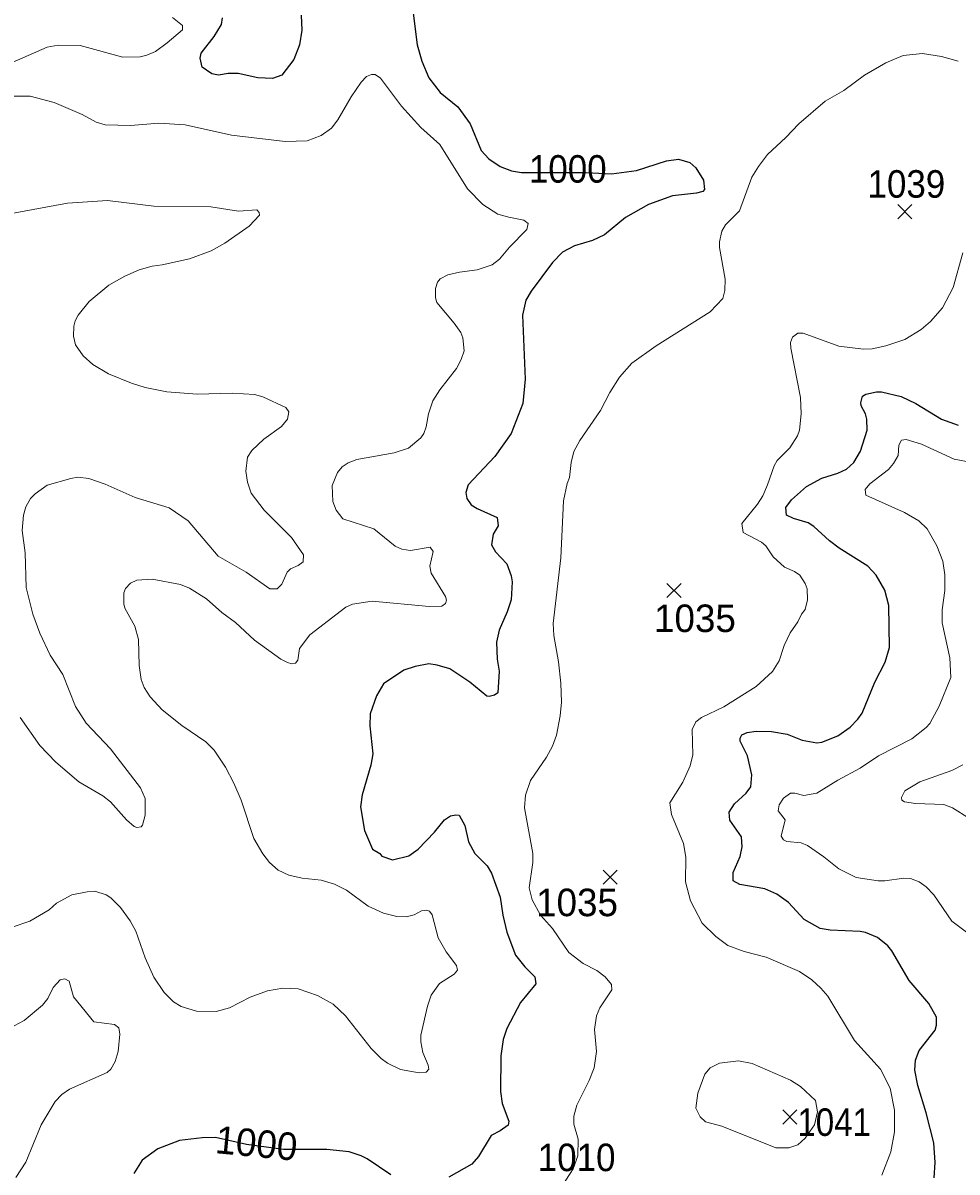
# Model space of a CAD drawing. Extents: x 265 to 291.4, y 7731.5 to 7759.6.
# Drawn here: x 269.927 to 272.644, y 7742.944 to 7746.284 of the extents above; entities that cross this region are included whole.
import ezdxf
from ezdxf.enums import TextEntityAlignment as Align

# ---------------------------------------------------------------- set-up
doc = ezdxf.new("R2010")
doc.units = 0
doc.header["$LTSCALE"] = 0.032
for name, color, linetype, lineweight in [('1', 7, 'Continuous', 25), ('2', 7, 'Continuous', 13), ('21', 7, 'Continuous', 25), ('61', 7, 'Continuous', 13)]:
    doc.layers.add(name, color=color, linetype=linetype, lineweight=lineweight)

msp = doc.modelspace()

# ---------------------------------------------------------------- linework, layer by layer
at = {"layer": '1'}
for points in [[(271.0575, 7746.352), (271.0742, 7746.22), (271.0877, 7746.1722), (271.1076, 7746.1245), (271.141, 7746.0815), (271.1919, 7746.0402), (271.2285, 7745.9909), (271.2603, 7745.9129), (271.2826, 7745.889), (271.3152, 7745.866), (271.3487, 7745.854), (271.3773, 7745.8492), (271.565, 7745.8489), (271.6394, 7745.8456), (271.7114, 7745.8548), (271.7989, 7745.8827), (271.8339, 7745.8874), (271.8673, 7745.8779), (271.884, 7745.8628), (271.9071, 7745.827), (271.9095, 7745.7992), (271.9047, 7745.7936), (271.8864, 7745.7888), (271.8164, 7745.7808), (271.7464, 7745.7562), (271.6796, 7745.718), (271.6191, 7745.6679), (271.5841, 7745.6512), (271.5316, 7745.6361), (271.4966, 7745.617), (271.468, 7745.5875), (271.4051, 7745.504), (271.39, 7745.4778), (271.3805, 7745.434), (271.3884, 7745.2479), (271.3813, 7745.1779), (271.3478, 7745.0904), (271.3001, 7745.0236), (271.2222, 7744.9408), (271.2158, 7744.9186), (271.2182, 7744.9011), (271.2309, 7744.8836), (271.2484, 7744.8724), (271.3065, 7744.8461), (271.3097, 7744.8223), (271.2953, 7744.7976), (271.2898, 7744.7666), (271.3017, 7744.7467), (271.3343, 7744.7117), (271.3478, 7744.6767)], [(270.4426, 7746.1818), (270.4458, 7746.1961), (270.4839, 7746.2446), (270.5046, 7746.2788), (270.5078, 7746.2987)], [(270.7361, 7746.3059), (270.7385, 7746.2629), (270.7313, 7746.22), (270.7154, 7746.177), (270.6805, 7746.1317), (270.6534, 7746.1221), (270.6105, 7746.1237)], [(270.6105, 7746.1237), (270.5532, 7746.1364), (270.5245, 7746.1372), (270.4959, 7746.1324), (270.4768, 7746.1356), (270.4482, 7746.1555), (270.4426, 7746.1818)], [(272.382, 7745.1317), (272.378, 7745.1477), (272.3653, 7745.1707), (272.3645, 7745.1795), (272.3692, 7745.1986), (272.3788, 7745.2049), (272.4098, 7745.2113), (272.4242, 7745.2113), (272.4814, 7745.1978), (272.5244, 7745.1779), (272.5992, 7745.1317), (272.6469, 7745.115)], [(272.2507, 7744.9607), (272.2969, 7744.975), (272.3223, 7744.9869), (272.3438, 7745.006), (272.3629, 7745.0395), (272.3828, 7745.0999), (272.382, 7745.1317)], [(272.5777, 7742.9267), (272.5808, 7742.9712), (272.5761, 7743.0285), (272.5546, 7743.116), (272.5299, 7743.1955), (272.5212, 7743.2401), (272.5236, 7743.2687), (272.5339, 7743.2974), (272.58, 7743.3562), (272.5848, 7743.3705), (272.5848, 7743.3936), (272.5617, 7743.4342), (272.5045, 7743.501), (272.4544, 7743.5869), (272.4432, 7743.6012), (272.413, 7743.6259), (272.378, 7743.6402), (272.3621, 7743.6434), (272.2746, 7743.6466), (272.246, 7743.6521), (272.199, 7743.6784), (272.1537, 7743.7269), (272.1203, 7743.7516), (272.0853, 7743.7675), (272.0121, 7743.7794), (271.993, 7743.7906), (271.993, 7743.8144), (272.0129, 7743.8606), (272.0192, 7743.8892), (272.0168, 7743.9178), (271.9834, 7743.9664), (271.981, 7743.9902), (271.9969, 7744.0141), (272.0312, 7744.0451), (272.0439, 7744.0634), (272.0471, 7744.0984), (272.0351, 7744.1533), (272.0129, 7744.1963), (272.0129, 7744.205), (272.0184, 7744.2146), (272.0336, 7744.2217), (272.0598, 7744.2257), (272.1044, 7744.2241), (272.1505, 7744.2161), (272.1935, 7744.1994), (272.2364, 7744.1915), (272.2507, 7744.193), (272.2969, 7744.2121), (272.3335, 7744.2368), (272.3557, 7744.2599), (272.3677, 7744.2774), (272.405, 7744.3681), (272.4353, 7744.4254), (272.4472, 7744.4683), (272.4456, 7744.5908), (272.4337, 7744.6354), (272.409, 7744.6783), (272.3844, 7744.7053), (272.3017, 7744.757), (272.273, 7744.7785), (272.2276, 7744.8199), (272.211, 7744.831), (272.168, 7744.843), (272.1481, 7744.8533), (272.1457, 7744.8756), (272.1624, 7744.8979), (272.2062, 7744.9368), (272.2507, 7744.9607)], [(271.3478, 7744.6767), (271.3502, 7744.6592), (271.3478, 7744.6067), (271.3359, 7744.5717), (271.3121, 7744.5192), (271.3049, 7744.4842), (271.3065, 7744.4349)], [(271.3065, 7744.4349), (271.3121, 7744.3999), (271.3089, 7744.3371), (271.2985, 7744.3299), (271.2834, 7744.3259), (271.277, 7744.3275), (271.2269, 7744.3681), (271.1689, 7744.4062), (271.1323, 7744.4174), (271.1076, 7744.4206), (271.0686, 7744.4134), (271.0352, 7744.4023), (270.9763, 7744.3625), (270.9557, 7744.3283), (270.9374, 7744.2758), (270.9358, 7744.2408), (270.9453, 7744.1597), (270.939, 7744.1263), (270.9143, 7744.0403), (270.9095, 7744.0053), (270.9207, 7743.9369), (270.9437, 7743.882), (270.9652, 7743.8693), (270.9716, 7743.8621), (271.0018, 7743.851), (271.0496, 7743.8629), (271.0766, 7743.8828), (271.1243, 7743.9313), (271.1537, 7743.9672), (271.1713, 7743.9791), (271.1864, 7743.9822), (271.1959, 7743.9807), (271.2126, 7743.9512), (271.2237, 7743.9035), (271.242, 7743.8701), (271.2771, 7743.8343), (271.2906, 7743.8128), (271.3152, 7743.7428), (271.3232, 7743.6903), (271.3351, 7743.641), (271.3598, 7743.5742), (271.3868, 7743.54), (271.4163, 7743.5113), (271.4186, 7743.4907), (271.3749, 7743.4366), (271.3351, 7743.361), (271.324, 7743.3292), (271.3168, 7743.2815), (271.316, 7743.178), (271.3216, 7743.143), (271.3407, 7743.0921), (271.3383, 7743.0802), (271.3153, 7743.0635), (271.289, 7743.05), (271.2524, 7742.9887), (271.2333, 7742.9672), (271.1657, 7742.929)], [(270.9971, 7742.9354), (270.9286, 7742.9823), (270.9111, 7742.9911), (270.8761, 7743.0022), (270.8109, 7743.0094), (270.6849, 7743.0099), (270.578, 7743.0239), (270.4877, 7743.0445), (270.4489, 7743.0438), (270.3829, 7743.0356), (270.3193, 7743.0118), (270.2739, 7742.9783), (270.2501, 7742.9394)]]:
    msp.add_lwpolyline(points, dxfattribs=at)
at = {"layer": '2'}
for points in [[(270.3623, 7746.2995), (270.3917, 7746.2764), (270.3917, 7746.2637), (270.3471, 7746.2255), (270.3129, 7746.2009), (270.2875, 7746.1897), (270.2684, 7746.185), (270.2175, 7746.1842), (270.0934, 7746.2184), (270.0297, 7746.2192), (269.9979, 7746.2136), (269.8722, 7746.1579)], [(272.6469, 7746.1722), (272.5992, 7746.1866), (272.5435, 7746.1945), (272.4878, 7746.1889), (272.4369, 7746.1675), (272.3748, 7746.1317), (272.3144, 7746.0871), (272.2603, 7746.0561), (272.1839, 7745.9909), (272.1457, 7745.9503), (272.0932, 7745.9018), (272.0662, 7745.8668), (272.0471, 7745.835), (272.0113, 7745.7379)], [(269.8929, 7746.0712), (269.9486, 7746.0712), (270.0186, 7746.0521), (270.0997, 7746.0179), (270.1403, 7745.9956), (270.1666, 7745.9877), (270.2398, 7745.9853), (270.3225, 7745.9924), (270.3989, 7745.9877), (270.5341, 7745.9575), (270.69, 7745.9392), (270.7536, 7745.9407), (270.795, 7745.9567), (270.8252, 7745.9781), (270.8435, 7746.002), (270.8817, 7746.0688), (270.9111, 7746.1118), (270.9263, 7746.1285), (270.9414, 7746.1341), (270.9517, 7746.1341), (270.9676, 7746.1229), (271.0281, 7746.0418), (271.0845, 7745.9797), (271.1394, 7745.9304), (271.2206, 7745.8015), (271.2651, 7745.7562), (271.3089, 7745.7284), (271.3407, 7745.7188), (271.3837, 7745.7109), (271.3972, 7745.7005), (271.3932, 7745.683), (271.3423, 7745.6321), (271.3137, 7745.5971), (271.2922, 7745.5804)], [(270.3082, 7745.7514), (270.1729, 7745.7681), (270.0568, 7745.7602), (269.8945, 7745.7299), (269.7943, 7745.7411), (269.7466, 7745.7506), (269.6479, 7745.7904)], [(269.9192, 7744.2655), (269.9764, 7744.1835), (270.0226, 7744.135), (270.0902, 7744.0785), (270.1602, 7744.0372), (270.1825, 7744.0197), (270.2286, 7743.9672), (270.2509, 7743.9481), (270.2588, 7743.9457), (270.2708, 7743.9473), (270.2755, 7743.952), (270.2827, 7743.9815), (270.2827, 7744.0292), (270.2692, 7744.061), (270.1817, 7744.174), (270.1109, 7744.2488), (270.0806, 7744.2973), (270.0433, 7744.3904), (270.0067, 7744.446), (269.9764, 7744.5097), (269.9566, 7744.5654), (269.9367, 7744.6433), (269.9343, 7744.7436), (269.9247, 7744.8088), (269.9287, 7744.8533), (269.9359, 7744.8772), (269.9494, 7744.9011), (269.9629, 7744.9154), (269.9979, 7744.94), (270.0663, 7744.9599), (270.087, 7744.9631), (270.1188, 7744.9599), (270.1666, 7744.9432), (270.2541, 7744.9042), (270.3527, 7744.8748), (270.4084, 7744.8366), (270.4951, 7744.734), (270.577, 7744.6871), (270.6455, 7744.6385), (270.6669, 7744.6385), (270.6804, 7744.6521), (270.6956, 7744.6879), (270.7051, 7744.6974), (270.7282, 7744.707), (270.7425, 7744.7173), (270.7433, 7744.738), (270.7083, 7744.7881), (270.6287, 7744.8676), (270.5914, 7744.917), (270.5802, 7744.9488), (270.5754, 7744.9806), (270.5802, 7745.022), (270.5929, 7745.0411), (270.628, 7745.0737), (270.6789, 7745.1111), (270.6964, 7745.1317), (270.7003, 7745.1532), (270.6924, 7745.1659), (270.6248, 7745.197), (270.6009, 7745.2041), (270.5373, 7745.2073), (270.4339, 7745.2049), (270.3463, 7745.2113), (270.2827, 7745.224), (270.2429, 7745.2367), (270.1761, 7745.2638), (270.1308, 7745.2908), (270.1021, 7745.3163), (270.0806, 7745.3481), (270.0743, 7745.3736), (270.0751, 7745.4022), (270.0791, 7745.4181), (270.0878, 7745.434), (270.1196, 7745.4738), (270.1769, 7745.5215), (270.2238, 7745.5478), (270.2652, 7745.5661), (270.3034, 7745.5772), (270.332, 7745.5804), (270.4116, 7745.5979), (270.4752, 7745.6218), (270.515, 7745.644), (270.585, 7745.6926), (270.6152, 7745.7252), (270.6144, 7745.7331), (270.6073, 7745.7403), (270.5548, 7745.7371), (270.4736, 7745.749), (270.3082, 7745.7514)], [(272.0113, 7745.7379), (271.9707, 7745.6965), (271.9596, 7745.679), (271.9532, 7745.6472), (271.9532, 7745.6313), (271.9699, 7745.539), (271.9691, 7745.5056)], [(272.4218, 7743.2425), (272.3462, 7743.326), (272.2682, 7743.4549), (272.2483, 7743.4787), (272.2221, 7743.5026), (272.1855, 7743.5265), (272.0885, 7743.5686), (272.0248, 7743.5853), (271.9771, 7743.6028), (271.9429, 7743.6283), (271.9031, 7743.6673), (271.8689, 7743.7317), (271.8546, 7743.7874), (271.8554, 7743.859), (271.8482, 7743.8987), (271.8132, 7743.9831), (271.8092, 7744.0173), (271.8466, 7744.0769), (271.8681, 7744.1247), (271.8753, 7744.1565), (271.8737, 7744.2297), (271.884, 7744.2527), (271.9007, 7744.2655), (271.9659, 7744.2957), (272.0598, 7744.3553), (272.1076, 7744.3991), (272.1266, 7744.4301), (272.141, 7744.4747), (272.1585, 7744.5113), (272.1815, 7744.5431), (272.1919, 7744.5654), (272.2022, 7744.5789), (272.2094, 7744.6067), (272.2078, 7744.6385), (272.2022, 7744.6545), (272.1871, 7744.6783), (272.1712, 7744.6895), (272.1426, 7744.7022), (272.1091, 7744.7324), (272.0877, 7744.7642), (272.0757, 7744.7746), (272.0216, 7744.8024), (272.0184, 7744.8287), (272.0638, 7744.8851), (272.0789, 7744.909), (272.0932, 7744.9408), (272.1123, 7744.9965), (272.1211, 7745.0124), (272.1577, 7745.049), (272.1799, 7745.084), (272.1855, 7745.0999), (272.1911, 7745.1477), (272.1887, 7745.1954), (272.1608, 7745.3386), (272.16, 7745.3545), (272.1656, 7745.3704), (272.1807, 7745.3823), (272.1966, 7745.3823), (272.3001, 7745.3441), (272.3717, 7745.3354), (272.3971, 7745.337), (272.4369, 7745.3449), (272.4926, 7745.364), (272.5395, 7745.3927), (272.5665, 7745.4157), (272.6015, 7745.4555), (272.6326, 7745.5152), (272.6612, 7745.6154)], [(271.2922, 7745.5804), (271.2484, 7745.5661), (271.1975, 7745.5597), (271.1633, 7745.5518), (271.141, 7745.5398), (271.1331, 7745.5303), (271.1275, 7745.512)], [(271.1275, 7745.512), (271.1275, 7745.4849), (271.1307, 7745.4714), (271.1816, 7745.411), (271.2007, 7745.3839), (271.2071, 7745.3688), (271.2102, 7745.3306), (271.2023, 7745.3052), (271.1888, 7745.2797), (271.1394, 7745.2177), (271.1196, 7745.1858), (271.1068, 7745.1477), (271.1005, 7745.1095), (271.0933, 7745.0904), (271.0846, 7745.0777), (271.0488, 7745.0474), (271.0066, 7745.0339), (270.8984, 7745.0148), (270.873, 7745.0053), (270.8563, 7744.9933), (270.8419, 7744.9774), (270.8268, 7744.9392), (270.8284, 7744.8931), (270.838, 7744.8676), (270.8578, 7744.8422), (270.9477, 7744.8135), (271.0098, 7744.7626), (271.0289, 7744.7539), (271.0543, 7744.7507), (271.1116, 7744.7602), (271.1204, 7744.7475), (271.1108, 7744.7052), (271.1148, 7744.6847), (271.1561, 7744.6163), (271.1596, 7744.6058), (271.1566, 7744.5959), (271.146, 7744.5886), (271.1084, 7744.5876), (270.943, 7744.6035), (270.8857, 7744.594), (270.8666, 7744.586), (270.7616, 7744.5057), (270.7314, 7744.4651), (270.7266, 7744.4317), (270.7202, 7744.423), (270.7091, 7744.4214), (270.6964, 7744.4245), (270.6773, 7744.4349), (270.6009, 7744.4898), (270.546, 7744.5415), (270.5054, 7744.5701), (270.4617, 7744.6099), (270.4116, 7744.6409), (270.3861, 7744.6513), (270.3034, 7744.6672), (270.2588, 7744.664), (270.2398, 7744.6552), (270.2254, 7744.6401), (270.2207, 7744.6274), (270.2207, 7744.5956), (270.2238, 7744.5829), (270.2525, 7744.5304), (270.2636, 7744.4922), (270.2652, 7744.4158), (270.2716, 7744.3752), (270.2795, 7744.3522), (270.2978, 7744.3251), (270.3328, 7744.2869), (270.3893, 7744.2416), (270.4593, 7744.1939), (270.4832, 7744.17), (270.5166, 7744.1207), (270.5412, 7744.0745), (270.5619, 7744.0252), (270.5993, 7743.9131), (270.6248, 7743.8685), (270.6446, 7743.8431), (270.6701, 7743.8216), (270.7011, 7743.8065), (270.7393, 7743.7977), (270.795, 7743.7921), (270.8332, 7743.781), (270.8682, 7743.7627), (270.9318, 7743.7166), (270.9764, 7743.6967), (271.0146, 7743.6871), (271.0416, 7743.6855), (271.0655, 7743.6919), (271.0862, 7743.703), (271.1021, 7743.7046), (271.11, 7743.7022), (271.118, 7743.6919), (271.1355, 7743.6243), (271.1585, 7743.5837), (271.188, 7743.544)], [(271.9691, 7745.5056), (271.9628, 7745.4826), (271.9262, 7745.4436), (271.7687, 7745.3449), (271.6979, 7745.2948), (271.6621, 7745.2543), (271.6342, 7745.2097), (271.6072, 7745.1572), (271.5467, 7745.0697), (271.53, 7745.0379), (271.5221, 7745.0061), (271.5173, 7744.9623), (271.5101, 7744.9456), (271.4998, 7744.8947), (271.4918, 7744.7292), (271.4696, 7744.5383), (271.4712, 7744.5033), (271.4847, 7744.4269), (271.4918, 7744.3649), (271.4934, 7744.3092), (271.4902, 7744.2694), (271.4791, 7744.2138), (271.468, 7744.1819), (271.4505, 7744.1501), (271.4035, 7744.0817), (271.3892, 7744.0388), (271.386, 7744.0022), (271.4107, 7743.8701), (271.4107, 7743.8439), (271.3996, 7743.7699), (271.4083, 7743.7349), (271.4322, 7743.6903), (271.468, 7743.6513), (271.5149, 7743.5821), (271.5571, 7743.5503), (271.5969, 7743.5296), (271.6207, 7743.5113), (271.639, 7743.4891), (271.6398, 7743.4732), (271.6048, 7743.4215), (271.5953, 7743.3976), (271.5897, 7743.3578), (271.5953, 7743.2942), (271.5889, 7743.2472), (271.5746, 7743.2099), (271.538, 7743.1383), (271.5292, 7743.1064), (271.53, 7743.0834), (271.542, 7743.0396), (271.5412, 7742.9909), (271.5272, 7742.953), (271.4871, 7742.8901)], [(272.7065, 7743.6147), (272.6294, 7743.6728), (272.5761, 7743.7492), (272.5546, 7743.7731), (272.5339, 7743.7874), (272.5085, 7743.7969), (272.4894, 7743.7985), (272.4337, 7743.7906), (272.4146, 7743.7906), (272.351, 7743.8001), (272.3001, 7743.8248), (272.2571, 7743.8598), (272.2094, 7743.8932), (272.1903, 7743.9003), (272.1489, 7743.9051), (272.1394, 7743.9099), (272.133, 7743.9202), (272.1441, 7743.968), (272.1242, 7743.9934), (272.1266, 7744.0109), (272.1394, 7744.0308), (272.1601, 7744.0451), (272.1728, 7744.0451), (272.1982, 7744.0387), (272.2364, 7744.0451), (272.2977, 7744.0833), (272.3621, 7744.1175), (272.4154, 7744.1533), (272.5124, 7744.2034), (272.5546, 7744.236), (272.5649, 7744.2472), (272.592, 7744.2981), (272.6262, 7744.3808), (272.623, 7744.4381), (272.6007, 7744.5399), (272.6007, 7744.5781), (272.6087, 7744.6338), (272.6087, 7744.6799), (272.6023, 7744.7197), (272.5856, 7744.7642), (272.557, 7744.8136), (272.5331, 7744.8366), (272.491, 7744.8613), (272.3788, 7744.9114), (272.3772, 7744.9273), (272.3907, 7744.944), (272.4448, 7744.9854), (272.4591, 7745.0029), (272.4727, 7745.0267), (272.4743, 7745.057), (272.4822, 7745.0713), (272.4957, 7745.0729), (272.5403, 7745.0593), (272.6358, 7745.0156), (272.6867, 7745.006)], [(272.6612, 7744.127), (272.6294, 7744.1111), (272.5355, 7744.0785), (272.4918, 7744.0515), (272.4822, 7744.0324), (272.4838, 7744.0244), (272.491, 7744.0196), (272.5228, 7744.0149), (272.6055, 7744.0117), (272.631, 7744.0022), (272.6803, 7743.9719)], [(271.0846, 7743.3419), (271.0846, 7743.3228), (271.0909, 7743.291), (271.106, 7743.2544), (271.1076, 7743.2425), (271.0997, 7743.2345), (271.0798, 7743.2321), (271.0257, 7743.2417), (270.9875, 7743.26), (270.9692, 7743.2735), (270.9398, 7743.3029), (270.8658, 7743.3976), (270.8292, 7743.4318), (270.7839, 7743.4572), (270.7282, 7743.4763), (270.6836, 7743.4787), (270.6391, 7743.4708), (270.5882, 7743.4525), (270.5277, 7743.4207), (270.4895, 7743.4103), (270.4323, 7743.4111), (270.3877, 7743.4246), (270.3654, 7743.4389), (270.3384, 7743.466), (270.3082, 7743.5106), (270.2827, 7743.5662), (270.2557, 7743.6442), (270.2397, 7743.6744), (270.2111, 7743.7126), (270.1833, 7743.7412), (270.1698, 7743.7492), (270.1363, 7743.7603), (270.1141, 7743.7587), (270.0695, 7743.7492), (270.025, 7743.7253), (270.0035, 7743.7062), (269.947, 7743.6728), (269.8961, 7743.6553)], [(271.188, 7743.544), (271.1911, 7743.5304), (271.1816, 7743.5193), (271.1387, 7743.4922), (271.1148, 7743.458), (271.1037, 7743.4262), (271.0846, 7743.3419)], [(269.9017, 7743.369), (269.9311, 7743.3841), (269.9844, 7743.4294), (269.9995, 7743.4485), (270.0154, 7743.4803), (270.0353, 7743.5026), (270.0488, 7743.5058), (270.0616, 7743.4986), (270.0743, 7743.4533), (270.1339, 7743.3801), (270.1936, 7743.3729), (270.2063, 7743.3634), (270.2095, 7743.3451), (270.2047, 7743.2942), (270.1952, 7743.2655), (270.1833, 7743.2433), (270.1721, 7743.2337), (270.0632, 7743.1852), (270.0409, 7743.1693), (270.021, 7743.1486), (269.9804, 7743.081), (269.9359, 7742.9728), (269.9072, 7742.9283)], [(272.4249, 7742.9346), (272.452, 7743.003), (272.4623, 7743.0603), (272.4623, 7743.1239), (272.4496, 7743.1876), (272.4218, 7743.2425)]]:
    msp.add_lwpolyline(points, dxfattribs=at)
msp.add_lwpolyline([(272.2027, 7743.0427), (272.2297, 7743.0807), (272.2379, 7743.1192), (272.2324, 7743.1518), (272.1887, 7743.1923), (272.1601, 7743.2114), (272.0487, 7743.2592), (272.0089, 7743.2671), (271.9532, 7743.2608), (271.9262, 7743.2464), (271.9103, 7743.2281), (271.8904, 7743.1733), (271.8848, 7743.1295), (271.8967, 7743.1041), (271.9127, 7743.0897), (271.9596, 7743.077), (272.1171, 7743.0142), (272.1553, 7743.0142), (272.1807, 7743.0229)], close=True, dxfattribs=at)
at = {"layer": '21'}
for p, q in [((272.4715, 7745.7558), (272.5127, 7745.7146)), ((272.5127, 7745.7558), (272.4715, 7745.7146)), ((271.8001, 7744.6546), (271.8413, 7744.6134)), ((271.8413, 7744.6546), (271.8001, 7744.6134)), ((271.6148, 7743.8217), (271.656, 7743.7805)), ((271.656, 7743.8217), (271.6148, 7743.7805)), ((272.1373, 7743.1244), (272.1785, 7743.0832)), ((272.1785, 7743.1244), (272.1373, 7743.0832))]:
    msp.add_line(p, q, dxfattribs=at)

# ---------------------------------------------------------------- texts
at = {"layer": '61'}
for s, width, p in [('1000', 0.95, (271.5119, 7745.8195)), ('1039', 0.95, (272.4967, 7745.7758)), ('1041', 0.9, (272.2867, 7743.0489)), ('1010', 0.95, (271.5377, 7742.9465))]:
    msp.add_text(s, height=0.08, dxfattribs=dict(at, width=width)).set_placement(p, align=Align.CENTER)
for p in [(271.8818, 7744.5134), (271.5389, 7743.6875)]:
    msp.add_text('1035', height=0.08, dxfattribs=at).set_placement(p, align=Align.CENTER)
msp.add_text('1000', height=0.08, rotation=354.563, dxfattribs=at).set_placement((270.6029, 7742.9878), align=Align.CENTER)

doc.saveas('drawing.dxf')
